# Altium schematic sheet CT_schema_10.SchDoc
size 281 x 153 mm
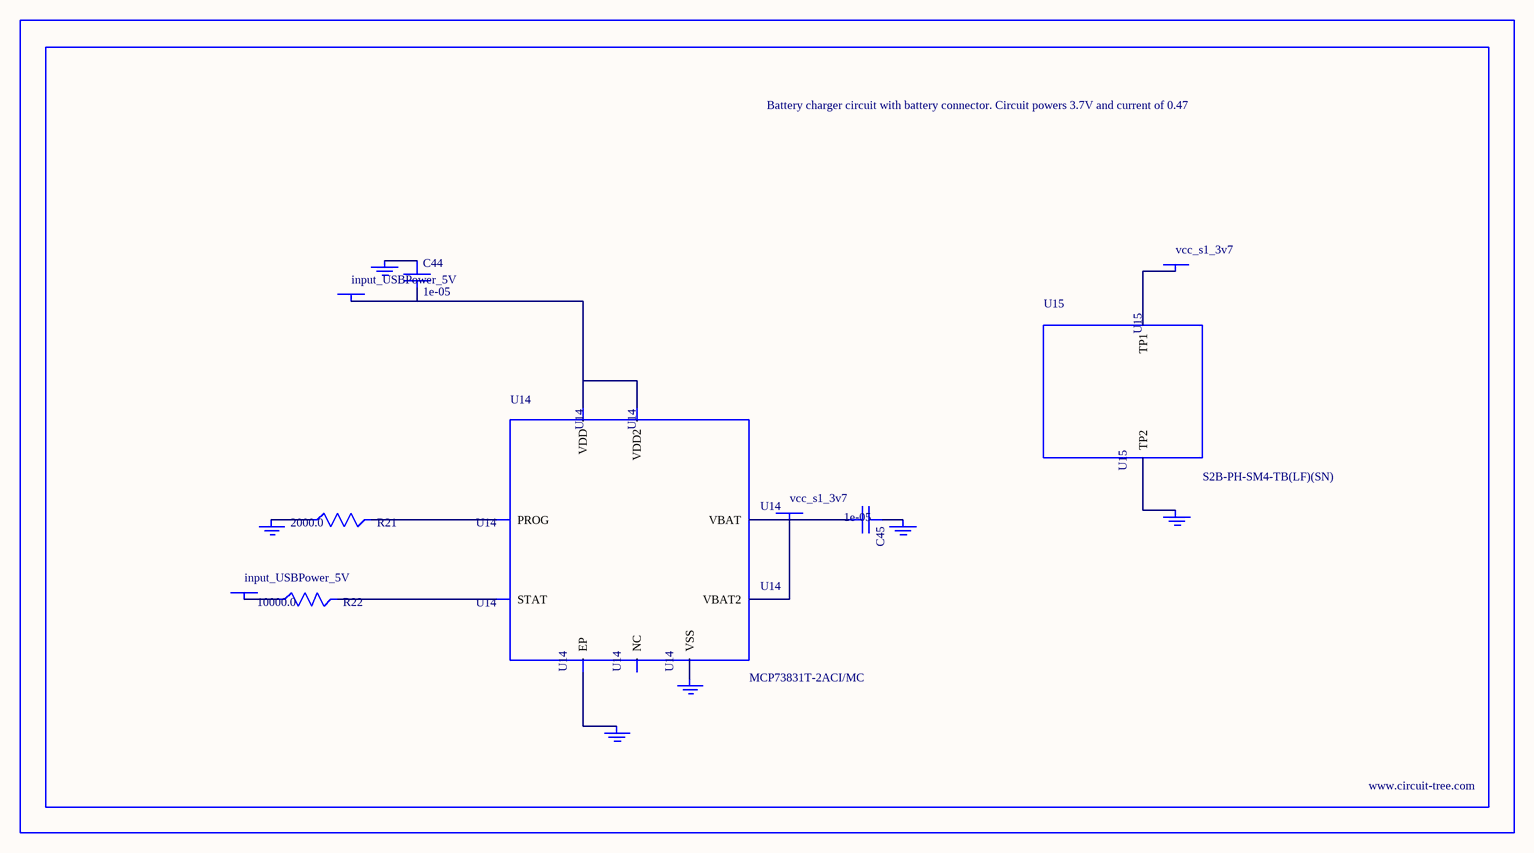
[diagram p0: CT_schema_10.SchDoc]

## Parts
BORDER9  (no value)
C44  1e-05  [C1206]
C45  1e-05  [C1206]
GND_INSTANCE_9_0  (no value)
GND_INSTANCE_9_1  (no value)
GND_INSTANCE_9_2  (no value)
GND_INSTANCE_9_3  (no value)
GND_INSTANCE_9_4  (no value)
GND_INSTANCE_9_5  (no value)
POWER_INSTANCE_9_0  input_USBPower_5V
POWER_INSTANCE_9_1  input_USBPower_5V
POWER_INSTANCE_9_2  vcc_s1_3v7
POWER_INSTANCE_9_3  vcc_s1_3v7
R21  2000.0  [R0603]
R22  10000.0  [R0603]
U14  MCP73831T-2ACI/MC  [DFN8_2X3MC]
U15  S2B-PH-SM4-TB(LF)(SN)  [JST-2-SMD]

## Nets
NetC44_1: C44.1 GND_INSTANCE_9_0.0(GND)
NetC44_2: C44.2 POWER_INSTANCE_9_0.0(PWR) U14.1(VDD) U14.2(VDD2)
NetC45_1: C45.1 GND_INSTANCE_9_1.0(GND)
NetC45_2: C45.2 POWER_INSTANCE_9_2.0(PWR) U14.3(VBAT) U14.4(VBAT2)
NetGND_INSTANCE_9_2_0: GND_INSTANCE_9_2.0(GND) R21.1
NetGND_INSTANCE_9_3_0: GND_INSTANCE_9_3.0(GND) U14.9(EP)
NetGND_INSTANCE_9_4_0: GND_INSTANCE_9_4.0(GND) U14.6(VSS)
NetGND_INSTANCE_9_5_0: GND_INSTANCE_9_5.0(GND) U15.2(TP2)
NetPOWER_INSTANCE_9_1_0: POWER_INSTANCE_9_1.0(PWR) R22.1
NetPOWER_INSTANCE_9_3_0: POWER_INSTANCE_9_3.0(PWR) U15.1(TP1)
NetR21_2: R21.2 U14.8(PROG)
NetR22_2: R22.2 U14.5(STAT)

Not connected (* = marked no-connect by the designer): U14 7(NC)

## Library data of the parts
BORDER9 = BORDER_PAGE9
C44 C45 = C1206C106K3RACTU
GND_INSTANCE_9_0-GND_INSTANCE_9_5 = GND
POWER_INSTANCE_9_0-POWER_INSTANCE_9_3 = PWR
R21 = RC0603JR-072KL
R22 = RC0603JR-0710KL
